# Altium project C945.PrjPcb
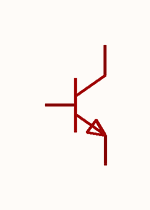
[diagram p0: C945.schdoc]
1 sheet, 1 parts. Net scope: global (net labels, ports and power ports of the same name join across sheets).

## Sheet C945.schdoc
size 127 x 101 mm

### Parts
Q?  c945(range:200-400)  [SOT-23-3_L2.9-W1.3-P1.90-LS2.4-BR]  (value not drawn)

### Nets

Not connected (* = marked no-connect by the designer): Q? 1(B) 2(E) 3(C)

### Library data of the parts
Q? = c945(range:200-400): 晶体管类型:NPN;集电极电流(Ic):150mA;集射极击穿电压(Vceo):50V;耗散功率(Pd):200mW;直流电流增益(hFE):200;; Manufacturer: CJ(江苏长电/长晶); AddInBom: yes; ModelId: c62791f0466c4ae2a892c056b845b0ca; ModelName: SOT-23-3P_L2.9-W1.3-H1.0-LS2.4-P0.95; ModelTransform: 98.425,114.173,0,180,0,0,0.0005,-0.0005,0; type: NPN; Current - Collector(Ic): 150mA; Collector - Emitter Voltage VCEO: 50V; Pd - Power Dissipation: 200mW; DC Current Gain: 200; Transition frequency(fT): 150MHz; Current - Collector Cutoff: 100nA; Vce Saturation(VCE(sat)): 300mV; Emitter-Base Voltage(Vebo): 5V; Number: 1个NPN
